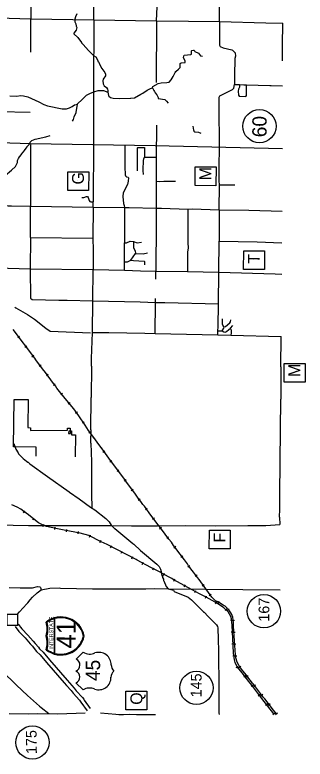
# Model space of a CAD drawing. Extents: x 299354 to 1325680, y 96128 to 228242.
# Drawn here: x 371846 to 396196, y 96128 to 158651 of the extents above; entities that cross this region are included whole.
import ezdxf

# ---------------------------------------------------------------- set-up
doc = ezdxf.new("R2010")
doc.units = 0
for name, color, linetype in [('Level 12', 7, 'Continuous'), ('Level 13', 7, 'Continuous'), ('Level 2', 7, 'Continuous'), ('Level 3', 7, 'Continuous'), ('Level 4', 7, 'Continuous'), ('Level 57', 7, 'Continuous')]:
    doc.layers.add(name, color=color, linetype=linetype)

msp = doc.modelspace()

# ---------------------------------------------------------------- linework, layer by layer
at = {"layer": 'Level 12'}
for p, q in [((392368, 149300), (392368, 149300)), ((392746, 108554), (392746, 108554)), ((375138, 107921), (375131, 105029)), ((375197, 105010), (375205, 107940)), ((376986, 104526), (377585, 105121)), ((378392, 103565), (378392, 103565)), ((376969, 102539), (377563, 101939)), ((387082, 102116), (387082, 102116)), ((373317, 97526), (373317, 97526))]:
    msp.add_line(p, q, dxfattribs=at)
for centre in [(392368, 149300), (392746, 108554), (387082, 102116), (373317, 97526)]:
    msp.add_circle(centre, 1398, dxfattribs=at)
for centre, radius, start, end in [((372557, 107066), 1999, 342.85526, 16.84224), ((375707, 106074), 1999, 11.38318, 128.17727), ((372557, 107066), 2066, 343.41917, 15.55857), ((375707, 106074), 1933, 107.10123, 126.84215), ((375707, 106074), 1933, 11.78677, 105.04344), ((372554, 105898), 1999, 342.85021, 16.83719), ((375709, 106873), 1999, 231.51518, 348.30927), ((372554, 105898), 2066, 344.13388, 16.27328), ((375709, 106873), 1933, 254.64901, 347.90568), ((375709, 106873), 1933, 232.8503, 252.59122), ((378145, 105985), 1030, 237.08064, 293.96268), ((378892, 104069), 1030, 357.57652, 108.67221), ((376753, 104030), 548, 292.88621, 64.83764), ((380676, 104059), 755, 181.01023, 225.04402), ((376748, 103022), 548, 294.69631, 66.64775), ((380663, 102977), 755, 133.5398, 178.52373), ((378878, 102981), 1030, 250.86174, 1.95744), ((378116, 101071), 1030, 65.57128, 122.45331)]:
    msp.add_arc(centre, radius, start, end, dxfattribs=at)
at = {"layer": 'Level 13'}
for p, q in [((387822, 145124), (387822, 145124)), ((377138, 144710), (377138, 144710)), ((391897, 138079), (391897, 138079)), ((395296, 128607), (395296, 128607)), ((389013, 114602), (389013, 114602)), ((382014, 101075), (382014, 101075))]:
    msp.add_line(p, q, dxfattribs=at)
for points in [[(388715, 144302), (386965, 144310), (386972, 145880), (388722, 145872)], [(378032, 143888), (376282, 143895), (376288, 145465), (378038, 145458)], [(392790, 137257), (391040, 137264), (391047, 138834), (392797, 138827)], [(396190, 127786), (394440, 127793), (394446, 129363), (396196, 129356)], [(389907, 113780), (388157, 113787), (388163, 115357), (389913, 115350)], [(382908, 100254), (381158, 100261), (381164, 101831), (382914, 101824)]]:
    msp.add_lwpolyline(points, close=True, dxfattribs=at)
at = {"layer": 'Level 2'}
for points in [[(378481, 158223), (378535, 164106)], [(389022, 158094), (389075, 163928)], [(378481, 158223), (378428, 152515), (378451, 151315), (378435, 149640), (378453, 147932), (378407, 142932)], [(389022, 158094), (389003, 156120), (389069, 155994), (389310, 155892), (390051, 155718), (390100, 155701), (390323, 155474), (390354, 155174), (390311, 154999), (390264, 153550), (390274, 152800)], [(389012, 144378), (388998, 144719), (389002, 148694), (388979, 149870), (388980, 151745), (389047, 151844), (390103, 152393), (390221, 152500), (390274, 152800)], [(361934, 148141), (367913, 148013), (373151, 147857), (383612, 147688), (394289, 147417)], [(388992, 142278), (389012, 144378)], [(378403, 142490), (378407, 142932)], [(378403, 142490), (378395, 139882)], [(388992, 142278), (388985, 139653)], [(378395, 139882), (378419, 138882), (378404, 137257)], [(388944, 137028), (388985, 139653)], [(378380, 134632), (378404, 137257)], [(378404, 137257), (381031, 137200)], [(381031, 137200), (382373, 137154)], [(382373, 137154), (383674, 137126)], [(383674, 137126), (386318, 137102)], [(386318, 137102), (388944, 137028)], [(388920, 134386), (388944, 137028)], [(388944, 137028), (393688, 136902), (394232, 136882)], [(378355, 131957), (378380, 134632)], [(388882, 132112), (388902, 132453), (388920, 134386)], [(378284, 129792), (378355, 131957)], [(388862, 131762), (388882, 132112)], [(388862, 131762), (389963, 131752)], [(389963, 131752), (394182, 131630)], [(394158, 129089), (394182, 131630)], [(378263, 129149), (378284, 129792)], [(378263, 129149), (378255, 126508)], [(394158, 129089), (394150, 126364)], [(378213, 123791), (378255, 126508)], [(394101, 121122), (394150, 126364)], [(378213, 123791), (378225, 123250)], [(378220, 122675), (378225, 123250)], [(371756, 122650), (371927, 122157), (372108, 121872), (372157, 121779), (372545, 121376), (372818, 121148), (372934, 121064)], [(378220, 122675), (378272, 121099)], [(372934, 121064), (372967, 121064), (373100, 120929), (374583, 119882), (376397, 118591), (376439, 118557), (377243, 118008), (378187, 117308), (378543, 117063), (379479, 116346), (379752, 116061), (379933, 115784), (380172, 115532), (380238, 115489), (381753, 114242), (381819, 114192), (382390, 113662), (383755, 112516), (383954, 112322), (384068, 112088), (384117, 111888), (384188, 111529), (384221, 111495), (384237, 111378), (384302, 111236), (384318, 111136), (384351, 111102), (384547, 110642), (384720, 110440), (385153, 110320)], [(378272, 121099), (378280, 118391)], [(394075, 118298), (394101, 121122)], [(378280, 118391), (378292, 117225)], [(394070, 117723), (394075, 118298)], [(394064, 117114), (394070, 117723)], [(394058, 116456), (394064, 117114)], [(394058, 116456), (394069, 115839)], [(379961, 115750), (381617, 115735)], [(381617, 115735), (383577, 115734)], [(383577, 115734), (383818, 115732), (386137, 115744)], [(386137, 115744), (388714, 115721)], [(388714, 115721), (391391, 115764)], [(391391, 115764), (392901, 115767), (394069, 115839)], [(364473, 110676), (364879, 110362), (365036, 110160), (365134, 109959), (365182, 109767), (365203, 108400), (365268, 108175), (365350, 108041), (365349, 107991), (365603, 107480), (365603, 107447), (365924, 107002), (366305, 106690), (366727, 106420), (368246, 105623), (368769, 105351), (369059, 105140), (369473, 104770), (371977, 102339), (372903, 101480), (373913, 100580), (374045, 100453), (374683, 99957)], [(372940, 109258), (373128, 109512), (373322, 109727), (373709, 110098), (374053, 110362)], [(374053, 110362), (374763, 110481), (375564, 110507), (375664, 110489)], [(375664, 110489), (377016, 110460)], [(377016, 110460), (378357, 110431)], [(378357, 110431), (379683, 110436)], [(379683, 110436), (382819, 110441)], [(382819, 110441), (383595, 110451)], [(383595, 110451), (384720, 110440)], [(384720, 110440), (394109, 110350)], [(385153, 110320), (385210, 110211), (386373, 109725), (386672, 109506), (387680, 108514), (387680, 108480), (387730, 108463), (388068, 108118), (388308, 107866), (388771, 107420), (388844, 107270), (388877, 107153), (388901, 106169), (388926, 105219), (388946, 102035), (388944, 100019), (388974, 99863)], [(372045, 108283), (372243, 108487), (372841, 109173), (372965, 109279)], [(371862, 107266), (372175, 106858), (372693, 106320), (373128, 105812)], [(372124, 107467), (372425, 107074), (372938, 106542), (373379, 106026)], [(373135, 105803), (373312, 105624), (373560, 105322), (373664, 105181), (373965, 104883), (374497, 104241), (375991, 102536), (376181, 102309), (376560, 101882), (376733, 101663), (377255, 101082), (377334, 100987), (377366, 100907), (377910, 100192)], [(373371, 106035), (373558, 105845), (373821, 105525), (373915, 105397), (374209, 105106), (374749, 104455), (376242, 102750), (376431, 102524), (376813, 102094), (376985, 101876), (377504, 101298), (377622, 101158), (377656, 101070), (378172, 100391)], [(371363, 99969), (373010, 99941)], [(373010, 99941), (373740, 99948)], [(373740, 99948), (375450, 99932), (377746, 100028)], [(379040, 100018), (380311, 99905), (380570, 99886)], [(380570, 99886), (380903, 99866)], [(380903, 99866), (380945, 99883)], [(380945, 99883), (381471, 99895)], [(381471, 99895), (382063, 99873)], [(382063, 99873), (383656, 99884)]]:
    msp.add_lwpolyline(points, dxfattribs=at)
msp.add_lwpolyline([(371171, 107371), (372091, 107367), (372094, 108286), (371175, 108290)], close=True, dxfattribs=at)
at = {"layer": 'Level 3'}
for points in [[(369066, 115849), (372985, 115763)], [(372985, 115763), (375679, 115756)], [(375679, 115756), (377422, 115740), (379961, 115750)]]:
    msp.add_lwpolyline(points, dxfattribs=at)
at = {"layer": 'Level 4'}
for p, q in [((372081, 131536), (372241, 131656)), ((372681, 130736), (372841, 130856)), ((373280, 129936), (373440, 130056)), ((373878, 129134), (374037, 129254)), ((374484, 128342), (374646, 128458)), ((375074, 127527), (375229, 127654)), ((375686, 126739), (375843, 126863)), ((376324, 125964), (376476, 126093)), ((376944, 125190), (377106, 125308)), ((377504, 124367), (377671, 124477)), ((378057, 123528), (378218, 123648)), ((379236, 121915), (379398, 122031)), ((379823, 121103), (379983, 121222)), ((380420, 120301), (380580, 120420)), ((381018, 119499), (381178, 119619)), ((381608, 118692), (381769, 118812)), ((382199, 117881), (382355, 118007)), ((372555, 116829), (372671, 116992)), ((382792, 117085), (382956, 117200)), ((373345, 116218), (373461, 116381)), ((383391, 116279), (383550, 116401)), ((374203, 115683), (374296, 115860)), ((375195, 115425), (375234, 115621)), ((376175, 115217), (376210, 115414)), ((377160, 115042), (377195, 115239)), ((383992, 115481), (384152, 115601)), ((378093, 114783), (378183, 114961)), ((378985, 114331), (379075, 114509)), ((384584, 114677), (384745, 114795)), ((379877, 113882), (379969, 114059)), ((385183, 113889), (385336, 114018)), ((380766, 113423), (380857, 113601)), ((385780, 113096), (385941, 113214)), ((381654, 112964), (381746, 113142)), ((382533, 112491), (382628, 112667)), ((383420, 112022), (383508, 112201)), ((386362, 112280), (386520, 112402)), ((384304, 111563), (384399, 111739)), ((386968, 111491), (387132, 111605)), ((385182, 111085), (385278, 111261)), ((386059, 110605), (386155, 110781)), ((387563, 110685), (387725, 110803)), ((386936, 110125), (387032, 110301)), ((387826, 109662), (387916, 109840)), ((388149, 109875), (388311, 109992)), ((388689, 109173), (388793, 109344)), ((388913, 109199), (389025, 109364)), ((389478, 108601), (389617, 108745)), ((389682, 108609), (389828, 108746)), ((389925, 107812), (390125, 107830)), ((390064, 107784), (390263, 107804)), ((389997, 106818), (390197, 106830)), ((390126, 106790), (390325, 106802)), ((390056, 105819), (390256, 105831)), ((390188, 105791), (390388, 105805)), ((390119, 104814), (390318, 104842)), ((390266, 104793), (390465, 104810)), ((390409, 103837), (390593, 103916)), ((390641, 103824), (390804, 103941)), ((391045, 103034), (391202, 103158)), ((391257, 103032), (391415, 103155)), ((391665, 102252), (391825, 102373)), ((391882, 102253), (392041, 102373)), ((392266, 101453), (392426, 101573)), ((392482, 101454), (392642, 101574)), ((392874, 100657), (393032, 100780)), ((393103, 100668), (393261, 100791)), ((393485, 99866), (393643, 99988)), ((393485, 99866), (393643, 99988)), ((393719, 99879), (393876, 100003))]:
    msp.add_line(p, q, dxfattribs=at)
for points in [[(373215, 164188), (373195, 158329)], [(383735, 158159), (383779, 159317), (383822, 164008)], [(368601, 158454), (373195, 158329)], [(373169, 155513), (373195, 158329)], [(373195, 158329), (378481, 158223)], [(378481, 158223), (383735, 158159)], [(383735, 158159), (383704, 152976)], [(383735, 158159), (386412, 158135)], [(386412, 158135), (389022, 158094)], [(389022, 158094), (392899, 157993)], [(392899, 157993), (394325, 157963)], [(394295, 154780), (394313, 156713), (394319, 157322), (394325, 157963)], [(390274, 152800), (390699, 152796)], [(390699, 152796), (390680, 152579), (390595, 152413), (390577, 152239), (390607, 151897), (390673, 151829), (391215, 151808), (391283, 151891), (391291, 152774)], [(390699, 152796), (391058, 152776), (391291, 152774)], [(391291, 152774), (393242, 152723), (393359, 152722), (394312, 152685)], [(367902, 150585), (373122, 150480)], [(383719, 149380), (383720, 149301), (383696, 146692)], [(373147, 147771), (373166, 142571)], [(381061, 147650), (381061, 145891), (381088, 145208), (381121, 145124), (381220, 145040), (381353, 145005), (381378, 144972), (381359, 144680), (381298, 144414), (380941, 143709), (380905, 143401), (380966, 142809), (381014, 142642), (381046, 142466)], [(382125, 145540), (382127, 147490), (382160, 147506), (382719, 147501), (382728, 146701)], [(382631, 145235), (382618, 145585), (382626, 146485), (382660, 146518), (382660, 146568), (382728, 146701)], [(382728, 146701), (383696, 146692)], [(383696, 146692), (383710, 144684)], [(383710, 144684), (383706, 142409)], [(383710, 144684), (383960, 144665), (384353, 144695), (385320, 144686)], [(389012, 144378), (390288, 144366)], [(377459, 143299), (377626, 143297), (377852, 143395), (377936, 143394), (378002, 143311), (378066, 143052), (378132, 142968), (378207, 142934), (378407, 142932)], [(368705, 142645), (371282, 142621), (371557, 142619), (373166, 142571)], [(373142, 139963), (373166, 142571)], [(373166, 142571), (378403, 142490)], [(378403, 142490), (381046, 142466)], [(381046, 142466), (381052, 139508)], [(381046, 142466), (381421, 142463), (383706, 142409)], [(383706, 142409), (383695, 141192), (383674, 137126)], [(383706, 142409), (384148, 142405), (386349, 142335)], [(386349, 142335), (386356, 139510), (386386, 139068), (386332, 138710), (386318, 137102)], [(386349, 142335), (386725, 142348), (388992, 142278)], [(388992, 142278), (391486, 142238), (394263, 142149)], [(373142, 139963), (373134, 137321)], [(373142, 139963), (378395, 139882)], [(381037, 137908), (381052, 139508)], [(381052, 139508), (381202, 139506), (381529, 139637), (381795, 139601)], [(381795, 139601), (381807, 139076), (381930, 138833), (381978, 138616)], [(381795, 139601), (382103, 139515), (382462, 139562)], [(388985, 139653), (392170, 139590), (394249, 139512)], [(381581, 138045), (381978, 138616)], [(381978, 138616), (382603, 138577), (382979, 138657)], [(381031, 137200), (381037, 137908)], [(381037, 137908), (381296, 137914), (381581, 138045)], [(381581, 138045), (381797, 138009), (382681, 137968), (382714, 137934), (382728, 137643)], [(368524, 137463), (373134, 137321)], [(373134, 137321), (373161, 134846), (373294, 134745), (375528, 134691), (376229, 134685), (378380, 134632)], [(373134, 137321), (378404, 137257)], [(383668, 136461), (383674, 137126)], [(378380, 134632), (382349, 134546)], [(382349, 134546), (383650, 134501)], [(383626, 131876), (383650, 134501)], [(383650, 134501), (383653, 134825)], [(383650, 134501), (384434, 134494), (388920, 134386)], [(389250, 133108), (389246, 132708), (389327, 132499), (389394, 132432)], [(389394, 132432), (389511, 132464), (389872, 132769), (389940, 132869), (389974, 133019)], [(389918, 132294), (389935, 132344), (390129, 132559)], [(375080, 127678), (374421, 128601), (374158, 128928), (373589, 129683), (373507, 129801), (371687, 132228)], [(378477, 123129), (378392, 123248), (378021, 123743), (377742, 124187), (377224, 124975), (376804, 125554), (376053, 126436), (375377, 127292), (375245, 127477), (375080, 127678), (374421, 128601), (374158, 128928), (373589, 129683), (373507, 129801), (371687, 132228)], [(378355, 131957), (379732, 131978), (382758, 131900), (383626, 131876)], [(388882, 132112), (389224, 132109)], [(389224, 132109), (389376, 132332), (389394, 132432)], [(389224, 132109), (389390, 132024), (389490, 132006), (389599, 132055), (389800, 132228), (389918, 132294)], [(389918, 132294), (389967, 132260), (390000, 132143), (389981, 131918), (389963, 131752)], [(383626, 131876), (388862, 131762)], [(376053, 126436), (375377, 127292), (375245, 127477), (375080, 127678)], [(373627, 121585), (373626, 122321), (371741, 122350), (371792, 126343), (372951, 126337), (372927, 123979), (373147, 123965), (373155, 123744), (376259, 123765), (376259, 123923), (376481, 123924), (376480, 123673), (376361, 123676), (376356, 123482), (376520, 123475), (376526, 123697), (376586, 123696), (376590, 123384), (376923, 123375), (376912, 121519)], [(377224, 124975), (376804, 125554), (376053, 126436)], [(377742, 124187), (377224, 124975)], [(379164, 122188), (378960, 122451), (378392, 123248), (378021, 123743), (377742, 124187)], [(393797, 99941), (393558, 100243), (392817, 101200), (392709, 101318), (391877, 102425), (391795, 102518), (391399, 103013), (391242, 103215), (390871, 103676), (390665, 103961), (390493, 104271), (390380, 104631), (390357, 104898), (390297, 105665), (390268, 106073), (390196, 107307), (390196, 107341), (390197, 107391), (390182, 107608), (390136, 108066), (390022, 108326), (389849, 108577), (389486, 108964), (389311, 109057), (389013, 109252), (388864, 109353), (388689, 109438), (388375, 109732), (387296, 111225), (387163, 111386), (387000, 111620), (386835, 111830), (386415, 112375), (386316, 112526), (386077, 112862), (385361, 113835), (385154, 114078), (385149, 114084), (385154, 114078), (384973, 114347), (384759, 114607), (384149, 115437), (383597, 116176), (383099, 116822), (382716, 117367), (382592, 117518), (382411, 117778), (382180, 118064), (381958, 118391), (381489, 119020), (381209, 119397), (381118, 119532), (379718, 121411), (379164, 122188), (379102, 122268)], [(381118, 119532), (379718, 121411), (379164, 122188)], [(383099, 116822), (382716, 117367), (382592, 117518), (382411, 117778), (382180, 118064), (381958, 118391), (381489, 119020), (381209, 119397), (381118, 119532)], [(375984, 115353), (375410, 115483), (374511, 115666), (374286, 115752), (373838, 115989), (373283, 116386), (372993, 116638), (372604, 116917), (372356, 117119), (372032, 117297), (371575, 117485)], [(393564, 99927), (392567, 101219), (391734, 102327), (391479, 102637), (391273, 102906), (390910, 103368), (390514, 103846), (390424, 104055), (390334, 104256), (390270, 104457), (390191, 105024), (390164, 105683), (390063, 107392), (390018, 107901), (389953, 108118), (389731, 108495), (389376, 108840), (388846, 109195), (388638, 109322), (387896, 109739), (387327, 110025), (386414, 110525), (385128, 111228), (385019, 111293), (384207, 111728), (384033, 111830), (383261, 112212), (382115, 112831), (382015, 112891), (379584, 114145), (379096, 114387), (378048, 114918), (377316, 115116), (375984, 115353), (375410, 115483), (374511, 115666), (374286, 115752), (373838, 115989), (373283, 116386), (372993, 116638), (372604, 116917), (372356, 117119), (372032, 117297), (371575, 117485)], [(385154, 114078), (384973, 114347), (384759, 114607), (384149, 115437), (383597, 116176), (383099, 116822)], [(379096, 114387), (378048, 114918), (377316, 115116), (375984, 115353)], [(382015, 112891), (379584, 114145), (379096, 114387)], [(387163, 111386), (387000, 111620), (386835, 111830), (386415, 112375), (386316, 112526), (386077, 112862), (385361, 113835), (385154, 114078), (385149, 114084)], [(385019, 111293), (384207, 111728), (384033, 111830), (383261, 112212), (382115, 112831), (382015, 112891)], [(387896, 109739), (387327, 110025), (386414, 110525), (385128, 111228), (385019, 111293)], [(389486, 108964), (389311, 109057), (389013, 109252), (388864, 109353), (388689, 109438), (388375, 109732), (387296, 111225), (387163, 111386)], [(371378, 110545), (372278, 110520)], [(372278, 110520), (373087, 110512)], [(373087, 110512), (373312, 110527), (373755, 110623), (373938, 110605), (374005, 110537), (374053, 110362)], [(389376, 108840), (388846, 109195), (388638, 109322), (387896, 109739)], [(390063, 107392), (390018, 107901), (389953, 108118), (389731, 108495), (389376, 108840)], [(390197, 107391), (390182, 107608), (390136, 108066), (390022, 108326), (389849, 108577), (389486, 108964)], [(390164, 105683), (390063, 107392)], [(390196, 107341), (390197, 107391)], [(390268, 106073), (390196, 107307), (390196, 107341)], [(390514, 103846), (390424, 104055), (390334, 104256), (390270, 104457), (390191, 105024), (390164, 105683)], [(390514, 103846), (390424, 104055), (390334, 104256), (390270, 104457), (390191, 105024), (390164, 105683)], [(393564, 99927), (392567, 101219), (391734, 102327), (391479, 102637), (391273, 102906), (390910, 103368), (390514, 103846), (390424, 104055), (390334, 104256), (390270, 104457), (390191, 105024), (390164, 105683)], [(390297, 105665), (390268, 106073)], [(390665, 103961), (390493, 104271), (390380, 104631), (390357, 104898), (390297, 105665)], [(391734, 102327), (391479, 102637), (391273, 102906), (390910, 103368), (390514, 103846)], [(391734, 102327), (391479, 102637), (391273, 102906), (390910, 103368), (390514, 103846)], [(391877, 102425), (391795, 102518), (391399, 103013), (391242, 103215), (390871, 103676), (390665, 103961)], [(392567, 101219), (391734, 102327)], [(392567, 101219), (391734, 102327)], [(392709, 101318), (391877, 102425)], [(393797, 99941), (393558, 100243), (392817, 101200), (392709, 101318)], [(393564, 99927), (392567, 101219)], [(393564, 99927), (392567, 101219)]]:
    msp.add_lwpolyline(points, dxfattribs=at)
at = {"layer": 'Level 57'}
for points in [[(377044, 158745), (376925, 158479), (376873, 158280), (376888, 158071), (376969, 157887), (376984, 157695), (377033, 157578), (376998, 157362), (376796, 157122), (376795, 157055), (377126, 156752), (377447, 156341), (377447, 156308), (377579, 156165), (378033, 155652), (378438, 155249), (378637, 155122), (378785, 154887), (378842, 154703), (378875, 154670), (378907, 154561), (379137, 154159), (379392, 153798), (379457, 153664), (379440, 153539), (379262, 153241), (379227, 153108), (379258, 152866), (379323, 152699), (379531, 152564), (379613, 152421), (379645, 152304), (379644, 152171)], [(386044, 155280), (386603, 155325), (386654, 155358), (386665, 155632), (386698, 155665), (386832, 155698), (386882, 155680), (386931, 155572), (387238, 155436), (387420, 155201), (387581, 155189)], [(383392, 152512), (383426, 152628), (383854, 152891), (384113, 152955), (384588, 152968), (384789, 152991), (384957, 153190), (385119, 153488), (385220, 153645), (385305, 153811), (385356, 153894), (385575, 154101), (385701, 154233), (385704, 154574), (385805, 154624), (386122, 154654), (386123, 154787), (385992, 155039), (386010, 155213), (386044, 155280)], [(377091, 151144), (377108, 151177), (377486, 151549), (377865, 151895), (378133, 152051), (378476, 152198), (378819, 152295), (379286, 152291), (379644, 152171)], [(379644, 152171), (379708, 151879), (379724, 151829), (379856, 151711), (380098, 151658), (380656, 151637), (381541, 151662), (381574, 151662), (381874, 151692), (382403, 151979)], [(382403, 151979), (382578, 152061), (382931, 152324), (383224, 152480), (383392, 152512)], [(383392, 152512), (383490, 152303), (383564, 152219), (383613, 152102), (383745, 151942), (383860, 151708), (383859, 151624)], [(371418, 151837), (371976, 151815), (372352, 151879), (372577, 151860), (372943, 151773), (373857, 151340), (374263, 151120), (374579, 151000), (375819, 150747), (376186, 150761), (376429, 150842), (376664, 150956), (376857, 151096), (377091, 151144)], [(383859, 151624), (384417, 151536), (384557, 151410), (384699, 151221)], [(376668, 149728), (376762, 149872), (376831, 150080), (376984, 150445), (377091, 151144)], [(386777, 149312), (386837, 148972), (386870, 148939), (386869, 148889), (386935, 148838), (387260, 148794), (387451, 148711)], [(373116, 147947), (373268, 148095), (373536, 148209), (374438, 148393), (374815, 148526)], [(370812, 144967), (370812, 145001), (371022, 145165), (371569, 145602), (371905, 145924), (372050, 146256), (372068, 146414), (372136, 146597), (372238, 146729), (372406, 146920), (372407, 146953), (372668, 147284), (372669, 147317), (372837, 147524), (372838, 147557), (373040, 147772), (373116, 147947)], [(371829, 134083), (371921, 134049), (372916, 133481), (373488, 133084), (374440, 132334), (374796, 132073), (378189, 131942)]]:
    msp.add_lwpolyline(points, dxfattribs=at)

# ---------------------------------------------------------------- texts
at = {"layer": 'Level 12'}
for s, height, rotation, p in [('60', 1200, 89.76698, (392964, 148371)), ('167', 900, 89.76698, (393192, 107673)), ('INTERSTATE', 319.9, 89.84622, (375057, 105355)), ('41', 1599.6, 89.84622, (376940, 105422)), ('45', 1200, 89.76698, (378989, 102684)), ('145', 900, 89.76698, (387503, 101313)), ('175', 900, 90.76697, (373689, 96563))]:
    msp.add_text(s, height=height, rotation=rotation, dxfattribs=at).set_placement(p)
at = {"layer": 'Level 13'}
for s, p in [('M', (388320, 144752)), ('G', (377637, 144400)), ('T', (392395, 137754)), ('M', (395795, 128235)), ('F', (389512, 114316)), ('Q', (382538, 100691))]:
    msp.add_text(s, height=1000, rotation=89.76698, dxfattribs=at).set_placement(p)

doc.saveas('drawing.dxf')
